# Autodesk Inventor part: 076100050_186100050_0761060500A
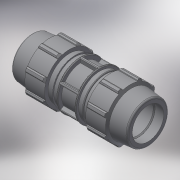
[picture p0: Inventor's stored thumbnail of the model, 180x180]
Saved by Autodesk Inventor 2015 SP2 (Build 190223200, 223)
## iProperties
Created: 2017-02
Part Number: 076100050_186100050_0761060500A
Material: Generic
Description: PLASSON REPAIR COUPLER 50
Document SubType Name: Modeling
Designer: KIM
Mass: 829.173 g
Surface Area: 1272.99 cm^2
Volume: 829.173 cm^3
Density: 1 g/cm^3
Appearance: Default
Author: KIM
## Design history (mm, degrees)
derived "07610.ipt"
feature "Solid1::07610.ipt"
tag "TaggingFeature1"
body "Solid1"
other parameters: "d1" = 244, "d4" = 20.33333, "d5" = 34.85714, "d7" = 96, "d8" = 72, "d9" = 34.85714, "d11" = 3.48571, "d12" = 76.8, "d13" = 120 deg, "d14" = 75, "d15" = 8 deg, "d16" = 86.4, "d18" = 2.5, "d19" = 35 deg, "d20" = 17.5 deg, "d21" = 89.28, "d23" = 0, "d25" = 360 deg, "d27" = 1.92, "d33" = 1, "d34" = 4.8, "d36" = 0, "d37" = 1, "d38" = 1, "d40" = 360 deg, "d42" = 43.92, "d43" = 2.88, "d46" = 1.5, "d50" = 9.41143, "d51" = 76.8, "E_" = 96, "H_" = 244, "l_" = 158, "d49" = 22.30857
